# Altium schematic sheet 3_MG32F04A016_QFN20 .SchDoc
size 292 x 220 mm; PageSetup: Record=PageOptions|CenterHorizontal=True|CenterVertical=True|PrintScale=0.94|XCorrection=1.00|YCorrection=1.00|PrintKind=0|BorderSize=5000000|LeftOffset=0|BottomOffset=0|Orientation=2|PaperLength=1000|PaperWidth=1000|Scale=100|PaperSource=7|PrintQuality=-4|MediaType=1|DitherType=10|PaperKind=A4 (210 x 297 mm)|PrintScaleMode=1
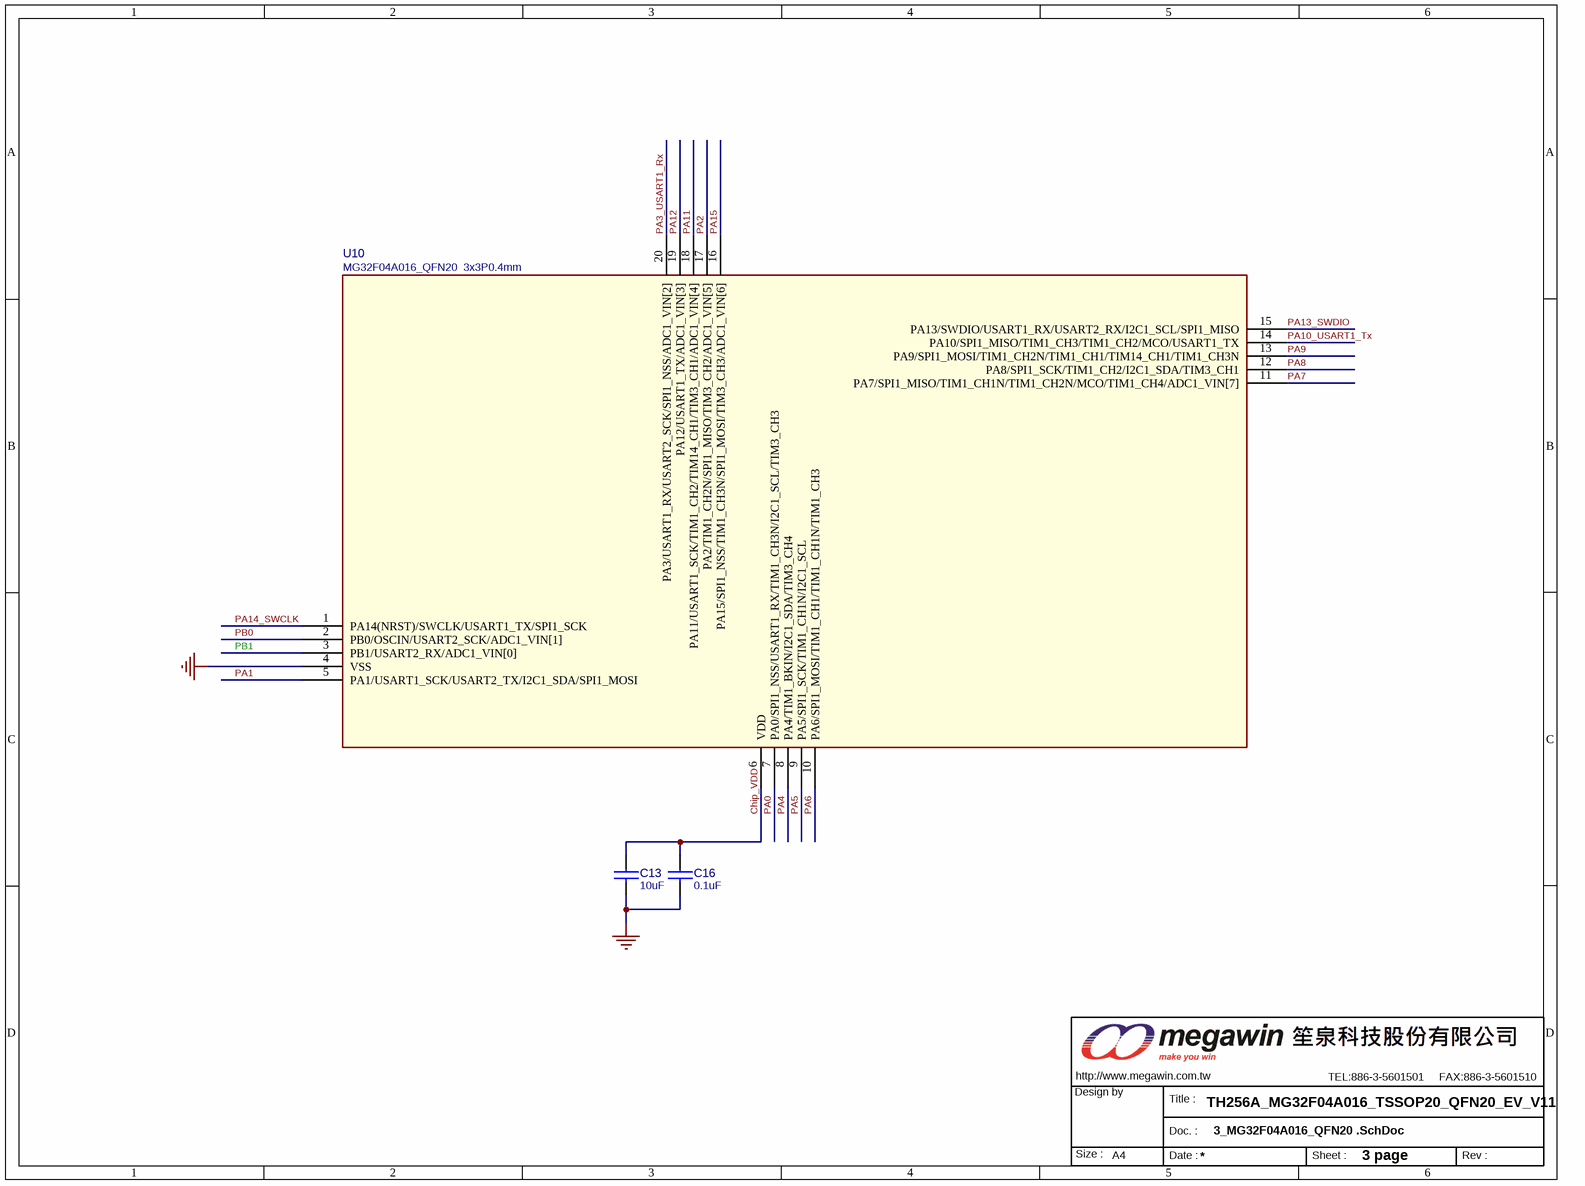
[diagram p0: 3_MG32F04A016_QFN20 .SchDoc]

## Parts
C13  10uF  [C-0603]
C16  0.1uF  [C-0603]
MW1  OrgAddr3: TEL:886-3-5601501     FAX:886-3-5601510  [MEGAWIN_3.4]  (hidden comment: MW-A4)  (graphical)
U10  MG32F04A016_QFN20  3x3P0.4mm  [QFN20_3X3P040_1]

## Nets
GND_POWER: C13.2 C16.2 U10.4(VSS)
Chip_VDD: C13.1 C16.1 U10.6(VDD)
PA0: U10.7(PA0/SPI1_NSS/USART1_RX/TIM1_CH3N/I2C1_SCL/TIM3_CH3)
PA1: U10.5(PA1/USART1_SCK/USART2_TX/I2C1_SDA/SPI1_MOSI)
PA2: U10.17(PA2/TIM1_CH2N/SPI1_MISO/TIM3_CH2/ADC1_VIN[5])
PA3_USART1_Rx: U10.20(PA3/USART1_RX/USART2_SCK/SPI1_NSS/ADC1_VIN[2])
PA4: U10.8(PA4/TIM1_BKIN/I2C1_SDA/TIM3_CH4)
PA5: U10.9(PA5/SPI1_SCK/TIM1_CH1N/I2C1_SCL)
PA6: U10.10(PA6/SPI1_MOSI/TIM1_CH1/TIM1_CH1N/TIM1_CH3)
PA7: U10.11(PA7/SPI1_MISO/TIM1_CH1N/TIM1_CH2N/MCO/TIM1_CH4/ADC1_VIN[7])
PA8: U10.12(PA8/SPI1_SCK/TIM1_CH2/I2C1_SDA/TIM3_CH1)
PA9: U10.13(PA9/SPI1_MOSI/TIM1_CH2N/TIM1_CH1/TIM14_CH1/TIM1_CH3N)
PA10_USART1_Tx: U10.14(PA10/SPI1_MISO/TIM1_CH3/TIM1_CH2/MCO/USART1_TX)
PA11: U10.18(PA11/USART1_SCK/TIM1_CH2/TIM14_CH1/TIM3_CH1/ADC1_VIN[4])
PA12: U10.19(PA12/USART1_TX/ADC1_VIN[3])
PA13_SWDIO: U10.15(PA13/SWDIO/USART1_RX/USART2_RX/I2C1_SCL/SPI1_MISO)
PA14_SWCLK: U10.1(PA14(NRST)/SWCLK/USART1_TX/SPI1_SCK)
PA15: U10.16(PA15/SPI1_NSS/TIM1_CH3N/SPI1_MOSI/TIM3_CH3/ADC1_VIN[6])
PB0: U10.2(PB0/OSCIN/USART2_SCK/ADC1_VIN[1])
PB1: U10.3(PB1/USART2_RX/ADC1_VIN[0])

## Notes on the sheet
- TH256A_MG32F04A016_TSSOP20_QFN20_EV_V11
- 3 page

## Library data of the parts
C13 C16 = CAP NP_Dup1
MW1 = MW_A4_2
U10 = MG32F003_QFN20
